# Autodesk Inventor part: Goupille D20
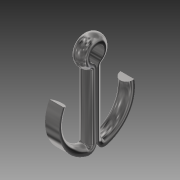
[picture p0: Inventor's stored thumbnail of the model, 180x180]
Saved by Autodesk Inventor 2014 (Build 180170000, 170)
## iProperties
Created: 2015-09
Part Number: Goupille D20
Material: Générique
Document SubType Name: Modeling
Designer: OL
Density: 1 g/cm^3
Appearance: Par défaut
Author: OL
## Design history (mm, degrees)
sketch "Esquisse1"
  geometry: L1 (-0.1, -22.656)-(-0.1, -1.771); L2 (0.1, -22.656)-(0.1, -1.771); A1 r 2.5 centre (0, 2.5) between (1.3, 0.365) and (-1.3, 0.365); A2 r 2.5 centre (2.6, -1.771) between (1.3, 0.365) and (0.1, -1.771); A3 r 2.5 centre (-2.6, -1.771) between (-0.1, -1.771) and (-1.3, 0.365); A4 r 12.5 centre (0, -13) between (-11.06, -7.175) and (-3.25, -25.07); A5 r 12.5 centre (0, -13) between (3.25, -25.07) and (12.309, -10.824); A6 r 2.5 centre (-2.6, -22.656) between (-3.25, -25.07) and (-0.1, -22.656); A7 r 2.5 centre (2.6, -22.656) between (0.1, -22.656) and (3.25, -25.07); 5 further points
  constraints: 19 point on circle, 8 tangent, 7 centre point, 4 end point, 4 point on line, 2 equal radius, 1 parallel, 1 vertical
  dimensions: "d2" = 5 diameter of A1; "d3" = 13 distance of A4.centre point (0, 0); "d4" = 0.2 distance between parallel lines of L2 L1; "d5" = 0.1 distance from line of point (0, 0) L1; "d6" = 2.5 radius of A2; "d7" = 0 horizontal distance of point (0, 0) A1.centre; "d8" = 2.5 radius of A6; "d12" = 12.5 radius of A4; "d13" = 12.5 radius of A5
sketch "Esquisse3"
  geometry: L1 (0, 5)-(0, 0.365) reference; L2 (-2.3, 5)-(2.3, 5); A1 r 2.3 centre (0, 5) between (2.3, 5) and (-2.3, 5); 2 further points
  constraints: 2 end point, 2 point on circle, 1 centre point, 1 coincident, 1 perpendicular
  dimensions: "d10" = 2.3 radius of A1
feature "Balayage2" sketch "Esquisse1", "Esquisse3" dims "d17" = 0
node "Solide2"
